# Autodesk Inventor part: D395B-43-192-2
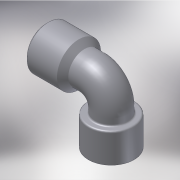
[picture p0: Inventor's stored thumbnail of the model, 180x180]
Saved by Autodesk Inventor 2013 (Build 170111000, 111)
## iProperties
Shininess: 25.0
Length Units: 11269
Angle Units: 11279
Time Units: 11290
Mass Units: 11283
Length Display Precision: 3
Angle Display Precision: 2
Created: 2002-08
Part Number: D395B-43-192-2
Document SubType Name: Modeling
Designer: SaAlex
Density: 1 g/cm^3
Material: Generic
Density: 0.0
Volumn: 0.0
Area: 0.0
PropertySet Name: Model Information
Control State: 0
Master: False
Checked Out: False
Checked Out Date: 2008-10-15
Last Check In Date: 2008-10-15
Author: SaAlex
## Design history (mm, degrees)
node "WorkPlane1"
sketch "Sketch1"
  geometry: L1 (-13, -1.75)-(-13, -23.75); L2 (22, 10.25)-(-1, 10.25); A1 r 12 centre (-1, -1.75) between (-1, 10.25) and (-13, -1.75)
  constraints: 4 end point, 2 point on circle, 2 tangent, 1 centre point, 1 horizontal, 1 vertical, 1 other
  dimensions: "d1" = 35 horizontal distance of L2.start L1.end; "d3" = 34 vertical distance of L1.end L2.start; "d5" = 12 radius of A1
node "WorkPlane2"
sweep "Sweep1" dims "d8" = 0
  node "Sketch2" dims "d7" = 20
node "WorkAxis1"
sketch "Sketch3"
  geometry: L1 (1, -23.75)-(-13, -23.75); L2 (1, -5.75)-(1, -23.75); L3 (-13, -5.75)-(1, -5.75); L4 (-13, -23.75)-(-13, -5.75); L5 (-23, -23.75)-(-3, -23.75) reference; L6 (-13, -23.75)-(-13, -5.75)
  constraints: 10 end point, 2 horizontal, 2 vertical
  dimensions: "d11" = 14 distance of L1.start L1.end; "d13" = 18 distance of L2.start L1.start
revolve "RevolutionFull1" sketch "Sketch3" stored, may be unused: angle "d15" = 360 deg
sketch "Sketch4"
  geometry: C1 r 14 at (0, 0) reference
hole "Hole2" sketch "Sketch4" diameter "d16" = 12; stored, may be unused: countersink angle "d20" = 82 deg, drill point angle "d22" = 120 deg; dims "d17" = 6, "d18" = 4, "d19" = 2, "d21" = 34
fillet "Fillet1" dims "d23" = 1
sketch "Sketch5"
  geometry: L1 (27, 10.25)-(3.5, 10.25); L2 (3.5, 10.25)-(3.5, 20.25); L3 (3.5, 20.25)-(7, 23.75); L4 (7, 23.75)-(27, 23.75); L5 (27, 23.75)-(27, 10.25); L6 (1, -23.75)-(-27, -23.75) reference; L7 (22, 20.25)-(22, 0.25) reference; L8 (27, 10.25)-(3.5, 10.25)
  constraints: 12 end point, 2 horizontal, 2 vertical
  dimensions: "d25" = 13.5 distance of L4.end L1.start; "d27" = 10 distance of L1.end L2.end; "d29" = 20 distance of L3.end L4.end; "d31" = 135 deg angle of L4 L3
revolve "RevolutionFull2" sketch "Sketch5" stored, may be unused: angle "d32" = 360 deg
sketch "Sketch6"
  geometry: C1 r 13.5 at (0, 0) reference; 1 further point
hole "Hole3" sketch "Sketch6" at (0, 0) diameter "d34" = 12; stored, may be unused: countersink angle "d38" = 37 deg, drill point angle "d40" = 120 deg; dims "d35" = 6, "d36" = 22, "d37" = 2, "d39" = 40
chamfer "Фаска1" distance "d41" = 1.6; stored, may be unused: angle "d42" = 45 deg, second distance "d43" = 1.6
body "Solid1"
other parameters: "d0" = 35 (derived), "d2" = 34 (derived), "d4" = 12 (derived), "d9" = 0, "d10" = 14 (derived), "d12" = 18 (derived), "d14" = 0 (derived), "d24" = 13.5 (derived), "d30" = 135 deg (derived), "d33" = 0
